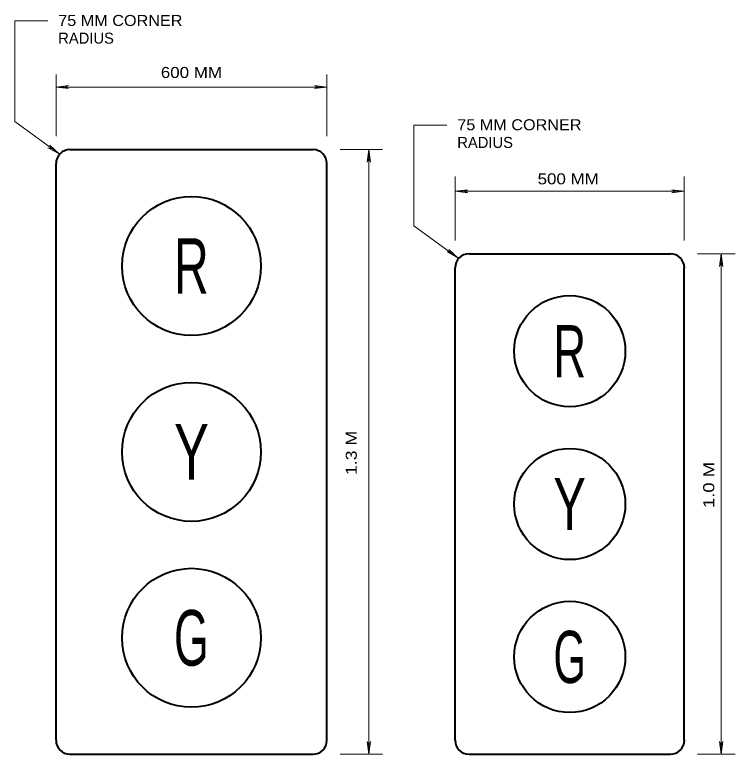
# Model space of a CAD drawing. Extents: x 312583 to 312853, y 144419 to 144586.
# Drawn here: x 312737.8 to 312787.5, y 144492.2 to 144543.2 of the extents above; entities that cross this region are included whole.
import ezdxf
from ezdxf.enums import TextEntityAlignment as Align

# ---------------------------------------------------------------- set-up
doc = ezdxf.new("R2010")
doc.units = 0
doc.header["$LTSCALE"] = 0.3
doc.layers.add('1', color=7, linetype='Continuous', lineweight=40)
doc.layers.add('2', color=7, linetype='Continuous', lineweight=13)

msp = doc.modelspace()

# ---------------------------------------------------------------- linework, layer by layer
at = {"layer": '1', "lineweight": 13}
for p, q in [((312737.768, 144542.7599), (312740.0527, 144542.7599)), ((312740.6124, 144538.2059), (312759.3037, 144538.2059)), ((312765.3065, 144535.5763), (312767.5835, 144535.5763)), ((312760.216, 144533.8896), (312763.129, 144533.8896)), ((312762.1951, 144492.2059), (312762.1951, 144533.8896)), ((312768.1508, 144531.0146), (312783.9595, 144531.0146)), ((312784.8795, 144526.7059), (312787.4707, 144526.7059)), ((312786.504, 144492.2059), (312786.504, 144526.7059)), ((312760.216, 144492.2059), (312763.129, 144492.2059)), ((312784.8795, 144492.2059), (312787.4707, 144492.2059))]:
    msp.add_line(p, q, dxfattribs=at)
at = {"layer": '1'}
for p, q in [((312741.5707, 144533.8896), (312758.3454, 144533.8896)), ((312740.6124, 144493.1643), (312740.6124, 144532.9313)), ((312759.3037, 144493.1643), (312759.3037, 144532.9313)), ((312769.1091, 144526.7059), (312783.0011, 144526.7059)), ((312768.1508, 144493.1643), (312768.1508, 144525.7476)), ((312783.9595, 144493.1643), (312783.9595, 144525.7476)), ((312741.5707, 144492.2059), (312758.3454, 144492.2059)), ((312769.1091, 144492.2059), (312783.0011, 144492.2059))]:
    msp.add_line(p, q, dxfattribs=at)
for centre, radius in [((312749.9576, 144525.8636), 4.7917), ((312776.0547, 144519.9935), 3.8333), ((312749.9576, 144513.0458), 4.7917), ((312776.0547, 144509.4519), 3.8333), ((312749.9576, 144500.2281), 4.7917), ((312776.0547, 144498.9107), 3.8333)]:
    msp.add_circle(centre, radius, dxfattribs=at)
for centre, start, end in [((312769.1067, 144493.1604), 180, 270), ((312783.0026, 144493.1604), 270, 0)]:
    msp.add_arc(centre, 0.9583, start, end, dxfattribs=at)
at = {"layer": '2'}
for p, q in [((312737.768, 144535.8216), (312737.768, 144542.7599)), ((312740.6124, 144534.8173), (312740.6124, 144539.0646)), ((312759.3037, 144534.8173), (312759.3037, 144539.0646)), ((312740.6124, 144538.2059), (312741.4787, 144538.3133)), ((312741.4787, 144538.3133), (312741.2027, 144538.2059)), ((312758.4374, 144538.3133), (312758.7134, 144538.2059)), ((312759.3037, 144538.2059), (312758.4374, 144538.3133)), ((312740.6124, 144538.2059), (312741.4787, 144538.0986)), ((312741.4787, 144538.0986), (312741.2027, 144538.2059)), ((312758.4374, 144538.0986), (312758.7134, 144538.2059)), ((312759.3037, 144538.2059), (312758.4374, 144538.0986)), ((312740.8194, 144533.5983), (312737.768, 144535.8216)), ((312765.3065, 144528.6379), (312765.3065, 144535.5763)), ((312740.183, 144534.1963), (312740.344, 144533.9433)), ((312740.8194, 144533.5983), (312740.183, 144534.1963)), ((312740.0527, 144534.0199), (312740.344, 144533.9433)), ((312740.8194, 144533.5983), (312740.0527, 144534.0199)), ((312762.1951, 144533.8896), (312762.0877, 144533.0233)), ((312762.1951, 144533.8896), (312762.3024, 144533.0233)), ((312762.0877, 144533.0233), (312762.1951, 144533.2993)), ((312762.3024, 144533.0233), (312762.1951, 144533.2993)), ((312768.1508, 144527.6336), (312768.1508, 144532.0343)), ((312783.9595, 144527.6336), (312783.9595, 144532.0343)), ((312768.1508, 144531.0146), (312769.0171, 144531.1219)), ((312768.1508, 144531.0146), (312769.0171, 144530.9073)), ((312769.0171, 144531.1219), (312768.7411, 144531.0146)), ((312769.0171, 144530.9073), (312768.7411, 144531.0146)), ((312783.0931, 144531.1219), (312783.3691, 144531.0146)), ((312783.9595, 144531.0146), (312783.0931, 144531.1219)), ((312783.0931, 144530.9073), (312783.3691, 144531.0146)), ((312783.9595, 144531.0146), (312783.0931, 144530.9073)), ((312768.3501, 144526.4069), (312765.3065, 144528.6379)), ((312767.5911, 144526.8363), (312767.8748, 144526.7596)), ((312768.3501, 144526.4069), (312767.5911, 144526.8363)), ((312767.7138, 144527.0049), (312767.8748, 144526.7596)), ((312768.3501, 144526.4069), (312767.7138, 144527.0049)), ((312786.504, 144526.7059), (312786.3967, 144525.8396)), ((312786.504, 144526.7059), (312786.6113, 144525.8396)), ((312786.3967, 144525.8396), (312786.504, 144526.1156)), ((312786.6113, 144525.8396), (312786.504, 144526.1156)), ((312762.0877, 144493.0723), (312762.1951, 144492.7963)), ((312762.1951, 144492.2059), (312762.0877, 144493.0723)), ((312762.3024, 144493.0723), (312762.1951, 144492.7963)), ((312762.1951, 144492.2059), (312762.3024, 144493.0723)), ((312786.3967, 144493.0723), (312786.504, 144492.7963)), ((312786.504, 144492.2059), (312786.3967, 144493.0723)), ((312786.6113, 144493.0723), (312786.504, 144492.7963)), ((312786.504, 144492.2059), (312786.6113, 144493.0723))]:
    msp.add_line(p, q, dxfattribs=at)
at = {"layer": '2', "lineweight": 40}
for centre, start, end in [((312741.5721, 144532.9313), 90, 180), ((312758.343, 144532.9313), 0, 90), ((312769.1067, 144525.7438), 90, 180), ((312783.0026, 144525.7438), 0, 90), ((312741.5721, 144493.1604), 180, 270), ((312758.343, 144493.1604), 270, 0)]:
    msp.add_arc(centre, 0.9583, start, end, dxfattribs=at)

# ---------------------------------------------------------------- texts
at = {"layer": '1'}
for s, height, width, p in [('R', 3.833, 0.65, (312749.9503, 144523.9459)), ('R', 3.594, 0.65, (312776.0513, 144518.1959)), ('Y', 3.833, 0.7, (312749.9581, 144511.1273)), ('Y', 3.594, 0.7, (312776.0475, 144507.6543)), ('G', 3.833, 0.6, (312749.9503, 144498.3086)), ('G', 3.594, 0.6, (312776.0513, 144497.1126))]:
    msp.add_text(s, height=height, dxfattribs=dict(at, width=width)).set_placement(p, align=Align.CENTER)
at = {"layer": '2'}
for s, width, p in [('75 MM CORNER', 1.1, (312740.7657, 144542.4139)), ('600 MM', 1.15, (312747.8431, 144538.8279)), ('75 MM CORNER', 1.1, (312768.2965, 144535.2226)), ('500 MM', 1.15, (312773.8378, 144531.4948))]:
    msp.add_text(s, height=0.76, dxfattribs=dict(at, width=width)).set_placement(p)
for p in [(312740.7657, 144541.1939), (312768.2965, 144534.0026)]:
    msp.add_text('RADIUS', height=0.76, dxfattribs=at).set_placement(p)
for s, width, p in [('1.3 M', 1.2, (312761.3612, 144511.45)), ('1.0 M', 1.25, (312786.0244, 144509.1747))]:
    msp.add_text(s, height=0.76, rotation=90, dxfattribs=dict(at, width=width)).set_placement(p)

doc.saveas('drawing.dxf')
